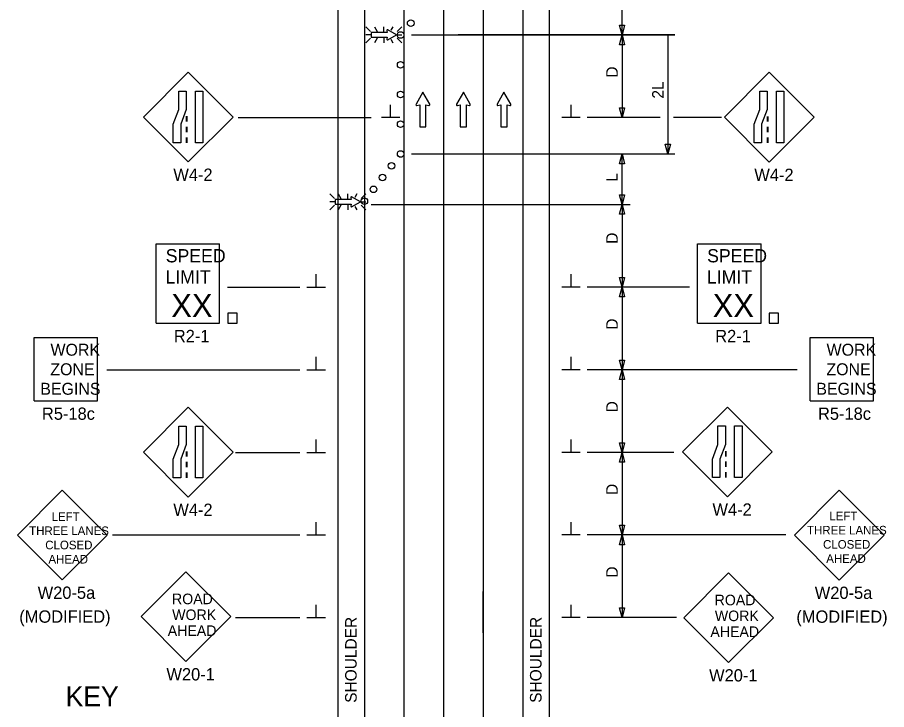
# Model space of a CAD drawing. Extents: x 16742 to 18475, y 7016 to 8203.
# Drawn here: x 16769 to 17296, y 7420 to 7839 of the extents above; entities that cross this region are included whole.
import ezdxf

# ---------------------------------------------------------------- set-up
doc = ezdxf.new("R2010")
doc.units = 0
for name, color, linetype in [('ALI_LEGAL_EX', 7, 'Continuous'), ('MT_SCRATCH_LEVEL_E', 7, 'Continuous'), ('PAVT_EDGE_EX', 7, 'Continuous'), ('TRAFFIC_SIGNS_PR', 7, 'Continuous'), ('TYPICAL_TEXT_DIMEN_EX', 7, 'Continuous'), ('TYPICAL_TEXT_DIMEN_PR', 7, 'Continuous')]:
    doc.layers.add(name, color=color, linetype=linetype)

msp = doc.modelspace()

# ---------------------------------------------------------------- linework, layer by layer
at = {"layer": 'ALI_LEGAL_EX'}
for p, q in [((17003.37, 8174.11), (17003.37, 7344.93)), ((17027.37, 8174.11), (17027.37, 7344.93)), ((17051.37, 8174.11), (17051.37, 7344.93)), ((17051.37, 8174.11), (17051.37, 7344.93)), ((17003.37, 8073.55), (17003.37, 7244.36)), ((17027.37, 8073.55), (17027.37, 7244.36)), ((17051.37, 8073.55), (17051.37, 7244.36)), ((17051.37, 8073.55), (17051.37, 7244.36))]:
    msp.add_line(p, q, dxfattribs=at)
for points in [[(17003.37, 7791.2), (17003.37, 7766.2)], [(17027.37, 7791.2), (17027.37, 7766.2)], [(17051.37, 7791.2), (17051.37, 7766.2)], [(17003.37, 7691.2), (17003.37, 7666.2)], [(17027.37, 7691.2), (17027.37, 7666.2)], [(17051.37, 7691.2), (17051.37, 7666.2)], [(17003.37, 7591.2), (17003.37, 7566.2)], [(17027.37, 7591.2), (17027.37, 7566.2)], [(17051.37, 7591.2), (17051.37, 7566.2)], [(17003.37, 7490.64), (17003.37, 7465.64)], [(17027.37, 7490.64), (17027.37, 7465.64)], [(17051.37, 7466.2), (17051.37, 7491.2)], [(17051.37, 7490.64), (17051.37, 7465.64)]]:
    msp.add_lwpolyline(points, dxfattribs=at)
at = {"layer": 'MT_SCRATCH_LEVEL_E'}
for p, q in [((17014.8, 7793.3), (17010.69, 7786.06)), ((17014.8, 7793.3), (17010.69, 7786.06)), ((17018.95, 7786.06), (17014.8, 7793.3)), ((17018.95, 7786.06), (17014.8, 7793.3)), ((17039.33, 7793.3), (17035.22, 7786.06)), ((17039.33, 7793.3), (17035.22, 7786.06)), ((17043.48, 7786.06), (17039.33, 7793.3)), ((17043.48, 7786.06), (17039.33, 7793.3)), ((17063.89, 7793.3), (17059.78, 7786.06)), ((17063.89, 7793.3), (17059.78, 7786.06)), ((17068.04, 7786.06), (17063.89, 7793.3)), ((17068.04, 7786.06), (17063.89, 7793.3)), ((17011.17, 7785.38), (17012.95, 7785.69)), ((17011.17, 7785.38), (17012.95, 7785.69)), ((17012.95, 7785.69), (17012.95, 7772.43)), ((17012.95, 7785.69), (17012.95, 7772.43)), ((17016.69, 7772.43), (17016.69, 7785.69)), ((17016.69, 7785.69), (17018.47, 7785.38)), ((17016.69, 7772.43), (17016.69, 7785.69)), ((17016.69, 7785.69), (17018.47, 7785.38)), ((17035.7, 7785.38), (17037.48, 7785.69)), ((17035.7, 7785.38), (17037.48, 7785.69)), ((17037.48, 7785.69), (17037.48, 7772.43)), ((17037.48, 7785.69), (17037.48, 7772.43)), ((17041.22, 7772.43), (17041.22, 7785.69)), ((17041.22, 7785.69), (17043, 7785.38)), ((17041.22, 7772.43), (17041.22, 7785.69)), ((17041.22, 7785.69), (17043, 7785.38)), ((17060.26, 7785.38), (17062.04, 7785.69)), ((17060.26, 7785.38), (17062.04, 7785.69)), ((17062.04, 7785.69), (17062.04, 7772.43)), ((17062.04, 7785.69), (17062.04, 7772.43)), ((17065.78, 7772.43), (17065.78, 7785.69)), ((17065.78, 7785.69), (17067.56, 7785.38)), ((17065.78, 7772.43), (17065.78, 7785.69)), ((17065.78, 7785.69), (17067.56, 7785.38)), ((17012.95, 7772.43), (17016.69, 7772.43)), ((17012.95, 7772.43), (17016.69, 7772.43)), ((17037.48, 7772.43), (17041.22, 7772.43)), ((17037.48, 7772.43), (17041.22, 7772.43)), ((17062.04, 7772.43), (17065.78, 7772.43)), ((17062.04, 7772.43), (17065.78, 7772.43))]:
    msp.add_line(p, q, dxfattribs=at)
for centre, start, end in [((17011.1, 7785.84), 150.4248, 279.9638), ((17011.1, 7785.84), 150.4248, 279.9638), ((17018.54, 7785.84), 260.0362, 29.7731), ((17018.54, 7785.84), 260.0362, 29.7731), ((17035.63, 7785.84), 150.4248, 279.9638), ((17035.63, 7785.84), 150.4248, 279.9638), ((17043.07, 7785.84), 260.0362, 29.7731), ((17043.07, 7785.84), 260.0362, 29.7731), ((17060.19, 7785.84), 150.4248, 279.9638), ((17060.19, 7785.84), 150.4248, 279.9638), ((17067.63, 7785.84), 260.0362, 29.7731), ((17067.63, 7785.84), 260.0362, 29.7731)]:
    msp.add_arc(centre, 0.463, start, end, dxfattribs=at)
at = {"layer": 'PAVT_EDGE_EX'}
for p, q in [((16963.37, 8203.06), (16963.37, 7352.47)), ((16979.37, 8203.06), (16979.37, 7352.47)), ((17075.37, 8203.06), (17075.37, 7352.47)), ((17091.37, 8203.06), (17091.37, 7352.47))]:
    msp.add_line(p, q, dxfattribs=at)
at = {"layer": 'TRAFFIC_SIGNS_PR'}
for p, q in [((16983.14, 7830.08), (16980.32, 7832.9)), ((16985.44, 7832.9), (16987.06, 7830.08)), ((16991.22, 7830.08), (16991.22, 7832.9)), ((16996.69, 7832.9), (16995.49, 7830.81)), ((17002.13, 7832.9), (16999.31, 7830.08)), ((16983.14, 7828.05), (16980.32, 7828.05)), ((16983.14, 7826.01), (16980.32, 7823.19)), ((16987.09, 7826.01), (16985.46, 7823.19)), ((16991.22, 7826.01), (16991.22, 7823.19)), ((16995.41, 7825.38), (16996.67, 7823.19)), ((16999.31, 7828.05), (17002.13, 7828.05)), ((17002.13, 7823.2), (16999.31, 7826.01)), ((16872.77, 7805.46), (16845.62, 7778.3)), ((16899.92, 7778.3), (16872.77, 7805.46)), ((17224.51, 7805.4), (17197.36, 7778.24)), ((17251.66, 7778.24), (17224.51, 7805.4)), ((16845.62, 7778.3), (16872.77, 7751.15)), ((16871.52, 7778.8), (16871.52, 7775.6)), ((16871.92, 7778.8), (16871.92, 7775.6)), ((16872.77, 7751.15), (16899.92, 7778.3)), ((17197.36, 7778.24), (17224.51, 7751.09)), ((17223.26, 7778.74), (17223.26, 7775.54)), ((17223.66, 7778.74), (17223.66, 7775.54)), ((17224.51, 7751.09), (17251.66, 7778.24)), ((16871.52, 7772.4), (16871.52, 7769.2)), ((16871.92, 7772.4), (16871.92, 7769.2)), ((17223.26, 7772.34), (17223.26, 7769.14)), ((17223.66, 7772.34), (17223.66, 7769.14)), ((16871.52, 7766), (16871.52, 7762.8)), ((16871.92, 7766), (16871.92, 7762.8)), ((17223.26, 7765.94), (17223.26, 7762.74)), ((17223.66, 7765.94), (17223.66, 7762.74)), ((16961.27, 7728.99), (16958.45, 7731.81)), ((16963.57, 7731.81), (16965.2, 7728.99)), ((16969.36, 7728.99), (16969.36, 7731.81)), ((16974.83, 7731.81), (16973.62, 7729.72)), ((16980.26, 7731.81), (16977.44, 7728.99)), ((16961.27, 7726.96), (16958.45, 7726.96)), ((16977.44, 7726.96), (16980.26, 7726.96)), ((16961.27, 7724.93), (16958.45, 7722.11)), ((16965.22, 7724.93), (16963.59, 7722.11)), ((16969.36, 7724.93), (16969.36, 7722.11)), ((16973.54, 7724.29), (16974.8, 7722.11)), ((16980.26, 7722.11), (16977.44, 7724.93)), ((16853.35, 7701.53), (16891.75, 7701.53)), ((16853.35, 7653.53), (16853.35, 7701.53)), ((16891.75, 7653.53), (16891.75, 7701.53)), ((17181.15, 7701.53), (17219.55, 7701.53)), ((17181.15, 7653.53), (17181.15, 7701.53)), ((17219.55, 7653.53), (17219.55, 7701.53)), ((16853.35, 7653.53), (16891.75, 7653.53)), ((17181.15, 7653.53), (17219.55, 7653.53)), ((16779.38, 7606.55), (16779.38, 7644.95)), ((16779.38, 7644.95), (16817.78, 7644.95)), ((16817.78, 7606.55), (16817.78, 7644.95)), ((17249.22, 7606.55), (17249.22, 7644.95)), ((17249.22, 7644.95), (17287.62, 7644.95)), ((17287.62, 7606.55), (17287.62, 7644.95)), ((16779.38, 7606.55), (16817.78, 7606.55)), ((17249.22, 7606.55), (17287.62, 7606.55)), ((16872.77, 7602.69), (16845.62, 7575.54)), ((16899.92, 7575.54), (16872.77, 7602.69)), ((17199.18, 7602.86), (17172.02, 7575.71)), ((17226.33, 7575.71), (17199.18, 7602.86)), ((16845.62, 7575.54), (16872.77, 7548.39)), ((16871.52, 7576.03), (16871.52, 7572.83)), ((16871.92, 7576.03), (16871.92, 7572.83)), ((16872.77, 7548.39), (16899.92, 7575.54)), ((17172.02, 7575.71), (17199.18, 7548.56)), ((17197.93, 7576.2), (17197.93, 7573)), ((17198.33, 7576.2), (17198.33, 7573)), ((17199.18, 7548.56), (17226.33, 7575.71)), ((16871.52, 7569.63), (16871.52, 7566.43)), ((16871.92, 7569.63), (16871.92, 7566.43)), ((17197.93, 7569.8), (17197.93, 7566.6)), ((17198.33, 7569.8), (17198.33, 7566.6)), ((16871.52, 7563.23), (16871.52, 7560.03)), ((16871.92, 7563.23), (16871.92, 7560.03)), ((17197.93, 7563.4), (17197.93, 7560.2)), ((17198.33, 7563.4), (17198.33, 7560.2)), ((16796.47, 7552.51), (16769.32, 7525.36)), ((16823.63, 7525.36), (16796.47, 7552.51)), ((17266.93, 7552.47), (17239.78, 7525.31)), ((17294.08, 7525.31), (17266.93, 7552.47)), ((16769.32, 7525.36), (16796.47, 7498.21)), ((16796.47, 7498.21), (16823.63, 7525.36)), ((17239.78, 7525.31), (17266.93, 7498.16)), ((17266.93, 7498.16), (17294.08, 7525.31)), ((16871.39, 7503.15), (16844.24, 7476)), ((16898.55, 7476), (16871.39, 7503.15)), ((17199.92, 7502.5), (17172.77, 7475.35)), ((17227.07, 7475.35), (17199.92, 7502.5)), ((16844.24, 7476), (16871.39, 7448.84)), ((16871.39, 7448.84), (16898.55, 7476)), ((17172.77, 7475.35), (17199.92, 7448.19)), ((17199.92, 7448.19), (17227.07, 7475.35))]:
    msp.add_line(p, q, dxfattribs=at)
for points in [[(16993.05, 7830.73), (16993.28, 7829.43), (16983.56, 7829.43), (16983.56, 7826.69), (16993.28, 7826.69), (16993.05, 7825.39)], [(16993.55, 7825.03), (16998.86, 7828.05), (16993.55, 7831.09)], [(16971.18, 7729.64), (16971.41, 7728.35), (16961.69, 7728.35), (16961.69, 7725.6), (16971.41, 7725.6), (16971.18, 7724.3)], [(16971.68, 7723.94), (16976.99, 7726.96), (16971.68, 7730)]]:
    msp.add_lwpolyline(points, dxfattribs=at)
for points in [[(16871.52, 7794.04), (16871.52, 7782.86), (16868.18, 7773.98), (16868.18, 7762.8), (16863.69, 7762.8), (16863.69, 7773.98), (16867.03, 7782.86), (16867.03, 7794.04)], [(16881.66, 7794.04), (16881.66, 7762.8), (16877.17, 7762.8), (16877.17, 7794.04)], [(17223.26, 7793.98), (17223.26, 7782.8), (17219.92, 7773.92), (17219.92, 7762.74), (17215.43, 7762.74), (17215.43, 7773.92), (17218.77, 7782.8), (17218.77, 7793.98)], [(17233.4, 7793.98), (17233.4, 7762.74), (17228.91, 7762.74), (17228.91, 7793.98)], [(16896.77, 7653.53), (16902.36, 7653.53), (16902.36, 7659.7), (16896.77, 7659.7)], [(17224.56, 7653.53), (17230.16, 7653.53), (17230.16, 7659.7), (17224.56, 7659.7)], [(16871.52, 7591.28), (16871.52, 7580.1), (16868.18, 7571.21), (16868.18, 7560.03), (16863.69, 7560.03), (16863.69, 7571.21), (16867.03, 7580.1), (16867.03, 7591.28)], [(16881.66, 7591.28), (16881.66, 7560.03), (16877.17, 7560.03), (16877.17, 7591.28)], [(17197.93, 7591.45), (17197.93, 7580.27), (17194.59, 7571.38), (17194.59, 7560.2), (17190.09, 7560.2), (17190.09, 7571.38), (17193.44, 7580.27), (17193.44, 7591.45)], [(17208.07, 7591.45), (17208.07, 7560.2), (17203.57, 7560.2), (17203.57, 7591.45)]]:
    msp.add_lwpolyline(points, close=True, dxfattribs=at)
for centre in [(17007.44, 7835.1), (17001.36, 7827.98), (17001.36, 7809.98), (17001.36, 7791.98), (17001.36, 7773.98), (17001.36, 7755.98), (16995.87, 7748.84), (16990.37, 7741.71), (16984.87, 7734.59), (16979.38, 7727.46)]:
    msp.add_circle(centre, 2, dxfattribs=at)
for centre, start, end in [((16993.39, 7830.79), 61.4833, 189.9593), ((16993.39, 7825.33), 170.7308, 298.8916), ((16971.52, 7729.7), 61.4833, 189.9593), ((16971.52, 7724.24), 170.7308, 298.8916)]:
    msp.add_arc(centre, 0.341, start, end, dxfattribs=at)
at = {"layer": 'TYPICAL_TEXT_DIMEN_PR'}
for p, q in [((17135.37, 7827.98), (17135.37, 7856.49)), ((17135.37, 7827.98), (17133.8, 7833.84)), ((17133.8, 7833.84), (17135.37, 7833.84)), ((17135.37, 7833.84), (17136.94, 7833.84)), ((17136.94, 7833.84), (17135.37, 7827.98)), ((17007.86, 7827.98), (17167.41, 7827.98)), ((17167.41, 7827.98), (17036.26, 7827.98)), ((17133.8, 7822.11), (17135.37, 7827.98)), ((17135.37, 7827.98), (17135.37, 7777.98)), ((17135.37, 7827.98), (17136.94, 7822.11)), ((17163.17, 7827.98), (17163.17, 7755.98)), ((17135.37, 7822.11), (17133.8, 7822.11)), ((17136.94, 7822.11), (17135.37, 7822.11)), ((16995.29, 7777.98), (16995.29, 7785.76)), ((17104.49, 7777.98), (17104.49, 7785.76)), ((17135.37, 7777.98), (17133.8, 7783.84)), ((17133.8, 7783.84), (17135.37, 7783.84)), ((17135.37, 7783.84), (17136.94, 7783.84)), ((17136.94, 7783.84), (17135.37, 7777.98)), ((16902.91, 7777.98), (16983.56, 7777.98)), ((17000.92, 7777.98), (16989.67, 7777.98)), ((17110.12, 7777.98), (17098.87, 7777.98)), ((17158.53, 7777.98), (17114.37, 7777.98)), ((17195.69, 7777.98), (17166.46, 7777.98)), ((17163.17, 7755.98), (17161.6, 7761.84)), ((17161.6, 7761.84), (17163.17, 7761.84)), ((17163.17, 7761.84), (17164.74, 7761.84)), ((17164.74, 7761.84), (17163.17, 7755.98)), ((17007.86, 7755.98), (17167.41, 7755.98)), ((17036.26, 7755.98), (17167.41, 7755.98)), ((17133.8, 7750.11), (17135.37, 7755.98)), ((17135.37, 7725.41), (17135.37, 7755.98)), ((17135.37, 7755.98), (17136.94, 7750.11)), ((17135.37, 7750.11), (17133.8, 7750.11)), ((17136.94, 7750.11), (17135.37, 7750.11)), ((17135.37, 7725.41), (17133.8, 7731.27)), ((17133.8, 7731.27), (17135.37, 7731.27)), ((17135.37, 7731.27), (17136.94, 7731.27)), ((17136.94, 7731.27), (17135.37, 7725.41)), ((16983.46, 7725.41), (17140.37, 7725.41)), ((17133.8, 7719.55), (17135.37, 7725.41)), ((17133.8, 7719.55), (17135.37, 7725.41)), ((17135.37, 7725.41), (17135.37, 7675.41)), ((17135.37, 7725.41), (17136.94, 7719.55)), ((17135.37, 7725.41), (17136.94, 7719.55)), ((17135.37, 7719.55), (17133.8, 7719.55)), ((17135.37, 7719.55), (17133.8, 7719.55)), ((17136.94, 7719.55), (17135.37, 7719.55)), ((17136.94, 7719.55), (17135.37, 7719.55)), ((16950.24, 7675.41), (16950.24, 7683.2)), ((17104.49, 7675.41), (17104.49, 7683.2)), ((17135.37, 7675.41), (17133.8, 7681.27)), ((17133.8, 7681.27), (17135.37, 7681.27)), ((17135.37, 7675.41), (17133.8, 7681.27)), ((17133.8, 7681.27), (17135.37, 7681.27)), ((17135.37, 7681.27), (17136.94, 7681.27)), ((17136.94, 7681.27), (17135.37, 7675.41)), ((17135.37, 7681.27), (17136.94, 7681.27)), ((17136.94, 7681.27), (17135.37, 7675.41)), ((16896.43, 7675.41), (16940.37, 7675.41)), ((16944.62, 7675.41), (16955.87, 7675.41)), ((17110.12, 7675.41), (17098.87, 7675.41)), ((17176.14, 7675.41), (17114.37, 7675.41)), ((17133.8, 7669.55), (17135.37, 7675.41)), ((17133.8, 7669.55), (17135.37, 7675.41)), ((17135.37, 7675.41), (17135.37, 7625.41)), ((17135.37, 7675.41), (17136.94, 7669.55)), ((17135.37, 7675.41), (17136.94, 7669.55)), ((17135.37, 7669.55), (17133.8, 7669.55)), ((17135.37, 7669.55), (17133.8, 7669.55)), ((17136.94, 7669.55), (17135.37, 7669.55)), ((17136.94, 7669.55), (17135.37, 7669.55)), ((16950.24, 7625.41), (16950.24, 7633.2)), ((17104.49, 7625.41), (17104.49, 7633.2)), ((17135.37, 7625.41), (17133.8, 7631.27)), ((17133.8, 7631.27), (17135.37, 7631.27)), ((17135.37, 7625.41), (17133.8, 7631.27)), ((17133.8, 7631.27), (17135.37, 7631.27)), ((17135.37, 7631.27), (17136.94, 7631.27)), ((17136.94, 7631.27), (17135.37, 7625.41)), ((17135.37, 7631.27), (17136.94, 7631.27)), ((17136.94, 7631.27), (17135.37, 7625.41)), ((16823.42, 7625.41), (16940.37, 7625.41)), ((16944.62, 7625.41), (16955.87, 7625.41)), ((17110.12, 7625.41), (17098.87, 7625.41)), ((17241.51, 7625.41), (17114.37, 7625.41)), ((17133.8, 7619.55), (17135.37, 7625.41)), ((17135.37, 7625.41), (17136.94, 7619.55)), ((17135.37, 7625.41), (17135.37, 7575.41)), ((17135.37, 7619.55), (17133.8, 7619.55)), ((17136.94, 7619.55), (17135.37, 7619.55)), ((16950.24, 7575.41), (16950.24, 7583.2)), ((17104.49, 7575.41), (17104.49, 7583.2)), ((17135.37, 7575.41), (17133.8, 7581.27)), ((17133.8, 7581.27), (17135.37, 7581.27)), ((17135.37, 7575.41), (17133.8, 7581.27)), ((17133.8, 7581.27), (17135.37, 7581.27)), ((17135.37, 7581.27), (17136.94, 7581.27)), ((17136.94, 7581.27), (17135.37, 7575.41)), ((17135.37, 7581.27), (17136.94, 7581.27)), ((17136.94, 7581.27), (17135.37, 7575.41)), ((16901.37, 7575.41), (16940.37, 7575.41)), ((16944.62, 7575.41), (16955.87, 7575.41)), ((17110.12, 7575.41), (17098.87, 7575.41)), ((17166.81, 7575.41), (17114.37, 7575.41)), ((17133.8, 7569.55), (17135.37, 7575.41)), ((17133.8, 7569.55), (17135.37, 7575.41)), ((17135.37, 7575.41), (17135.37, 7525.41)), ((17135.37, 7575.41), (17136.94, 7569.55)), ((17135.37, 7575.41), (17136.94, 7569.55)), ((17135.37, 7569.55), (17133.8, 7569.55)), ((17135.37, 7569.55), (17133.8, 7569.55)), ((17136.94, 7569.55), (17135.37, 7569.55)), ((17136.94, 7569.55), (17135.37, 7569.55)), ((16950.24, 7525.41), (16950.24, 7533.2)), ((17104.49, 7525.41), (17104.49, 7533.2)), ((17135.37, 7525.41), (17133.8, 7531.27)), ((17133.8, 7531.27), (17135.37, 7531.27)), ((17135.37, 7525.41), (17133.8, 7531.27)), ((17133.8, 7531.27), (17135.37, 7531.27)), ((17135.37, 7531.27), (17136.94, 7531.27)), ((17136.94, 7531.27), (17135.37, 7525.41)), ((17135.37, 7531.27), (17136.94, 7531.27)), ((17136.94, 7531.27), (17135.37, 7525.41)), ((16826.87, 7525.41), (16940.37, 7525.41)), ((16944.62, 7525.41), (16955.87, 7525.41)), ((17110.12, 7525.41), (17098.87, 7525.41)), ((17234.61, 7525.41), (17114.37, 7525.41)), ((17133.8, 7519.55), (17135.37, 7525.41)), ((17135.37, 7525.41), (17135.37, 7475.41)), ((17135.37, 7525.41), (17136.94, 7519.55)), ((17135.37, 7519.55), (17133.8, 7519.55)), ((17136.94, 7519.55), (17135.37, 7519.55)), ((16950.24, 7475.41), (16950.24, 7483.2)), ((17104.49, 7475.41), (17104.49, 7483.2)), ((17135.37, 7475.41), (17133.8, 7481.27)), ((17133.8, 7481.27), (17135.37, 7481.27)), ((17135.37, 7481.27), (17136.94, 7481.27)), ((17136.94, 7481.27), (17135.37, 7475.41)), ((16901.37, 7475.41), (16940.37, 7475.41)), ((16944.62, 7475.41), (16955.87, 7475.41)), ((17110.12, 7475.41), (17098.87, 7475.41)), ((17168.42, 7475.41), (17114.37, 7475.41))]:
    msp.add_line(p, q, dxfattribs=at)

# ---------------------------------------------------------------- texts
at = {"layer": 'TRAFFIC_SIGNS_PR'}
for s, height, p in [('W4-2', 7.44, (16863.73, 7739.71)), ('W4-2', 7.44, (17215.47, 7739.65)), ('SPEED', 8, (16859.12, 7690.39)), ('SPEED', 8, (17186.91, 7690.39)), ('LIMIT', 8, (16858.96, 7677.59)), ('LIMIT', 8, (17186.75, 7677.59)), ('XX', 14.031, (16862.46, 7657.29)), ('XX', 14.031, (17190.26, 7657.29)), ('R2-1', 7.44, (16864.03, 7642.09)), ('R2-1', 7.44, (17191.82, 7642.09)), ('WORK', 7.217, (16789.37, 7633.91)), ('WORK', 7.217, (17259.22, 7633.91)), ('ZONE', 7.217, (16789.26, 7622.1)), ('ZONE', 7.217, (17259.11, 7622.1)), ('BEGINS', 7.217, (16783.18, 7610.29)), ('BEGINS', 7.217, (17253.03, 7610.29)), ('R5-18c', 7.44, (16784.19, 7595.11)), ('R5-18c', 7.44, (17254.04, 7595.11)), ('W4-2', 7.44, (16863.73, 7536.95)), ('W4-2', 7.44, (17190.14, 7537.12)), ('LEFT', 5.2, (16790.01, 7533.95)), ('LEFT', 5.2, (17260.9, 7534.33)), ('THREE LANES', 5.2, (17247.35, 7525.73)), ('THREE LANES', 5.2, (16776.45, 7525.36)), ('CLOSED', 5.2, (16786.18, 7516.76)), ('CLOSED', 5.2, (17257.08, 7517.13)), ('AHEAD', 5.2, (16788.13, 7508.15)), ('AHEAD', 5.2, (17259.02, 7508.53)), ('W20-5a', 7.44, (16781.61, 7486.77)), ('W20-5a', 7.44, (17252.07, 7486.72)), ('ROAD', 6.4, (16862.93, 7483.53)), ('ROAD', 6.4, (17191.46, 7482.88)), ('(MODIFIED)', 7.44, (16770.47, 7472.33)), ('WORK', 6.4, (16863.04, 7473.93)), ('WORK', 6.4, (17191.57, 7473.28)), ('(MODIFIED)', 7.44, (17240.92, 7472.28)), ('AHEAD', 6.4, (16860.35, 7464.33)), ('AHEAD', 6.4, (17188.88, 7463.68)), ('W20-1', 7.44, (16859.56, 7437.4)), ('W20-1', 7.44, (17188.09, 7436.76))]:
    msp.add_text(s, height=height, dxfattribs=at).set_placement(p)
at = {"layer": 'TYPICAL_TEXT_DIMEN_EX'}
msp.add_text('KEY', height=12, dxfattribs=at).set_placement((16798.52, 7421.74))
at = {"layer": 'TYPICAL_TEXT_DIMEN_PR'}
for s, p in [('D', (17132.81, 7802.19)), ('2L', (17160.61, 7789.48)), ('L', (17132.81, 7739.27)), ('D', (17132.81, 7701.64)), ('D', (17132.81, 7649.63)), ('D', (17132.81, 7599.63)), ('D', (17132.81, 7549.63)), ('D', (17132.81, 7499.63)), ('SHOULDER', (16974.74, 7423.86)), ('SHOULDER', (17086.65, 7423.86))]:
    msp.add_text(s, height=7, rotation=90, dxfattribs=at).set_placement(p)

doc.saveas('drawing.dxf')
